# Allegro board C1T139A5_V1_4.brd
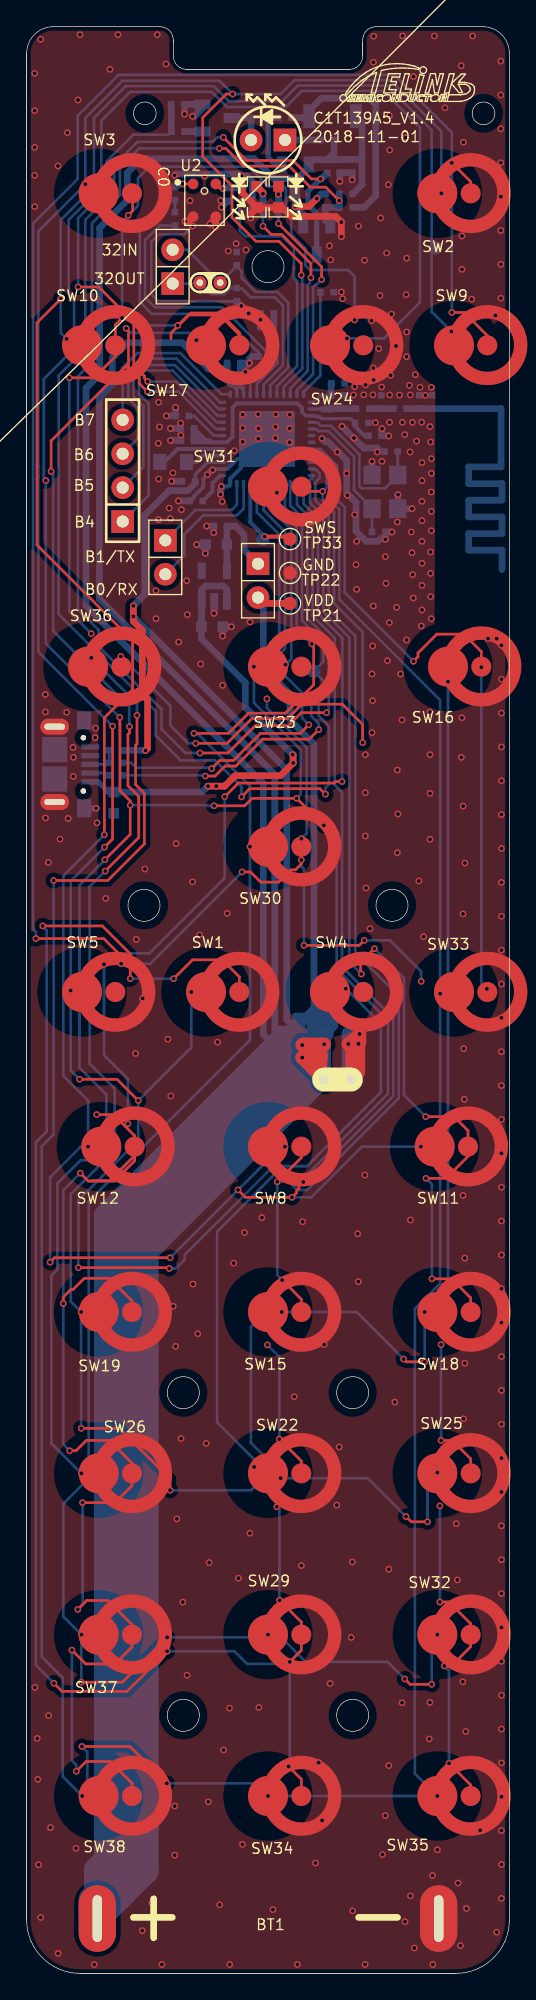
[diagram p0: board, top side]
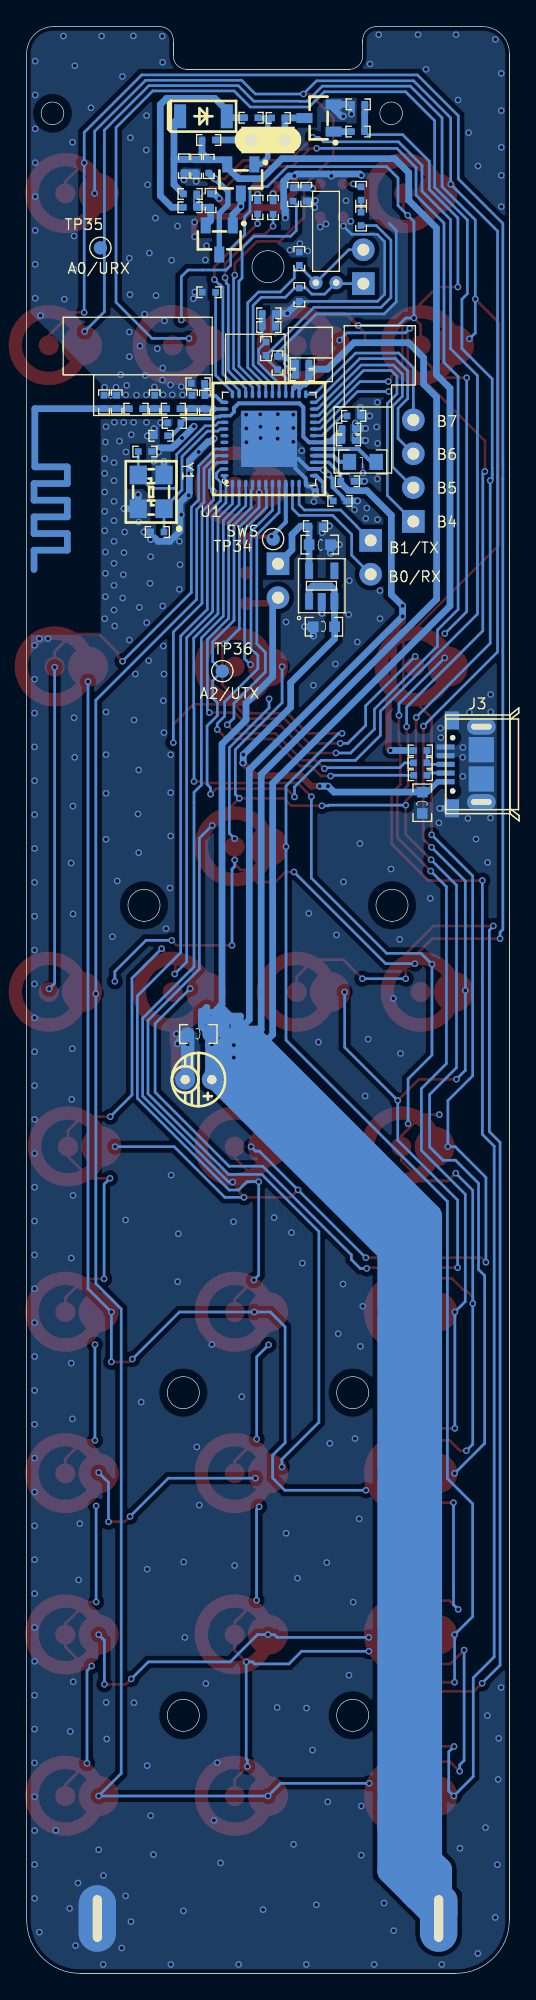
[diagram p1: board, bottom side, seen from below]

Outline 36.2 x 146 mm; copper layers: TOP, BOTTOM. Coordinates in mm from the lower left corner of the outline.
Outline path: circle c8.8,80.1 r1.2 ; circle c8.86,139.5 r0.85 ; circle c11.75,43.55 r1.2 ; circle c11.75,19.35 r1.2 ; circle c18.1,128 r1.2 ; circle c24.45,43.55 r1.2 ; circle c24.45,19.35 r1.2 ; circle c27.4,80.1 r1.2 ; circle c34.26,139.5 r0.85 ; 0,144 0,4 ; 0,144 arc(0.59,145.41) 2,146 10,146 arc(10.71,145.71) 11,145 ; 0,144 0,4 ; 0,4 arc(1.17,1.17) 4,0 ; 4,0 32.2,0 ; 4,0 32.2,0 ; 32.2,0 arc(35.03,1.17) 36.2,4 36.2,144 arc(35.61,145.41) 34.2,146 26.2,146 arc(25.49,145.71) 25.2,145 25.2,144.8 ; 11,145 11,144.8 ; 11,145 11,144.8 ; 11,144.8 11,143.8 arc(11.29,143.09) 12,142.8 ; 12,142.8 24.2,142.8 ; 12,142.8 24.2,142.8 ; 24.2,142.8 arc(24.91,143.09) 25.2,143.8 ; 25.2,144.8 25.2,143.8 ; 25.2,144.8 25.2,143.8

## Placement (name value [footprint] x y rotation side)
BT1  3V_2xAAA  [BAT_2DIP]  18.1 4.11 0 top
C1  0.1uF  [0402]  25.13 116.29 180 bottom
C2  2.2uF  [0402]  26.13 115.32 180 bottom
C4  1uF  [0402]  22.53 126.08 0 bottom
C7  1uF  [0402]  15.53 120.77 180 bottom
C8  1uF  [0402]  12.71 110.43 0 bottom
C10  1uF  [0402]  11.67 116.8 0 bottom
C12  4.7uF  [0402]  24.41 135.55 270 bottom
C13  4.7uF  [0402]  15.23 133.41 270 bottom
C16  10uF  [0603C]  23.33 70.45 0 bottom
C17  10pF  [0402]  17.39 120.78 90 bottom
C18  1uF  [0402]  11.12 133.49 90 bottom
C19  NC  [0402]  27.33 114.13 0 bottom
C20  NC  [0402]  26.4 108.1 180 bottom
C21  NC  [0402]  15.75 128.6 270 bottom
C22  NC  [0402]  15.75 125.9 90 bottom
C23  10pF  [0402]  18.04 123.48 180 bottom
C24  1uF  [0402]  18.04 124.5 180 bottom
C25  1uF  [0402]  12.06 114.96 180 bottom
C26  0.1uF  [0402]  23.49 135.52 270 bottom
C27  1uF  [0402]  12.14 111.91 0 bottom
C28  1uF  [0402]  15.53 119.84 180 bottom
C29  0.1uF  [0402]  12.05 115.86 0 bottom
C30  2.7pF  [0402C]  23.8 117.85 270 bottom
C31  18pF  [0402]  23.35 119.25 0 bottom
C32  2.2pF  [0402C]  26.6 117.85 270 bottom
C33  220pF  [0402C]  25.2 117.35 0 bottom
C34  1.5pF  [0402C]  29.45 117.85 270 bottom
C35  1.2pF  [0402]  30.4 117.85 270 bottom
C39  NC/10uF  [0603C]  13.9 101 0 bottom
C40  NC/10uF  [0603C]  14.22 107.15 180 bottom
C41  NC/0.1uF  [0402]  14.53 108.54 180 bottom
C42  NC/10uF  [0603C]  6.53 87.79 270 bottom
CD1  220uF/10V  [CD2P0_4P0B]  23.31 67.03 0 bottom
D1  Red_LED  [0603-LED]  17.25 133.23 270 top
D2  Red_LED  [0603-LED]  18.89 133.23 270 top
D4  1N4148  [SOD80]  22.94 139.28 180 bottom
D5  LED  [LED_TH_2P54MM_2PIN]  18.1 137.5 0 top
J3  NC/USB_MiniABF  [MICROUSB_DIP]  4.78 89.37 90 bottom
J5  NC/HEADER 4  [HDR254F-1X4X850]  7.2 116.51 270 top
J9  NC/HEADER 2  [HDR254F-1X2X850]  10.4 104.93 90 top
J10  HEADER 2  [HDR254F-1X2X850]  10.95 129.27 270 top
J36  NC/2PIN  [HDR254F-1X2X850]  17.35 103.18 90 top
L3  47UH  [0805L]  10.99 113.36 0 bottom
L4  1.3nH  [0402C]  22.83 117.82 270 bottom
L7  1.5nH  [0402C]  28 117.35 0 bottom
Q2  C1815  [SOT-23]  14.27 139.15 90 bottom
Q3  A1015  [SOT-23]  20.14 134.58 0 bottom
Q4  C1815  [SOT-23]  21.76 130 0 bottom
R1  1K  [0402]  18.88 132.45 90 bottom
R2  1K  [0402]  17.72 132.44 90 bottom
R3  0R  [0402]  16.22 133.41 90 bottom
R4  NC/1.5K  [0402]  6.68 91.71 0 bottom
R7  1  [0402]  22.55 137.5 0 bottom
R8  NC  [0402]  11.34 140.17 180 bottom
R9  100  [0402]  11.35 138.13 0 bottom
R10  10K  [0402]  22.54 135.52 90 bottom
R11  10K  [0402]  22.41 132.96 90 bottom
R12  NC  [0402]  23.94 133.45 180 bottom
R13  47K  [0402]  23.95 132.45 180 bottom
R14  22K  [0402]  19.37 139.17 0 bottom
R15  10K  [0402]  17.33 139.16 0 bottom
R16  NC  [0402]  18.25 121.85 90 bottom
R17  000R  [0402]  11.12 131.59 90 bottom
R69  NC/33  [0402]  6.69 90.79 180 bottom
R70  NC/33  [0402]  6.68 89.86 180 bottom
SW1  SW2PIN  [SW_OUT6_IN3]  13.45 73.6 180 top
SW2  SW2PIN  [SW_OUT6_IN3]  30.8 133.5 180 top
SW3  SW2PIN  [SW_OUT6_IN3]  5.4 133.5 180 top
SW4  SW2PIN  [SW_OUT6_IN3]  22.75 73.6 180 top
SW5  SW2PIN  [SW_OUT6_IN3]  4.15 73.6 180 top
SW8  SW2PIN  [SW_OUT6_IN3]  18.1 62 180 top
SW9  SW2PIN  [SW_OUT6_IN3]  32.05 122.1 180 top
SW10  SW2PIN  [SW_OUT6_IN3]  4.15 122.1 180 top
SW11  SW2PIN  [SW_OUT6_IN3]  30.6 62 180 top
SW12  SW2PIN  [SW_OUT6_IN3]  5.6 62 180 top
SW15  SW2PIN  [SW_OUT6_IN3]  18.1 49.6 180 top
SW16  SW2PIN  [SW_OUT6_IN3]  31.6 98 180 top
SW17  SW2PIN  [SW_OUT6_IN3]  13.45 122.1 180 top
SW18  SW2PIN  [SW_OUT6_IN3]  30.8 49.6 180 top
SW19  SW2PIN  [SW_OUT6_IN3]  5.4 49.6 180 top
SW22  SW2PIN  [SW_OUT6_IN3]  18.1 37.5 180 top
SW23  SW2PIN  [SW_OUT6_IN3]  18.1 98 180 top
SW24  SW2PIN  [SW_OUT6_IN3]  22.75 122.1 180 top
SW25  SW2PIN  [SW_OUT6_IN3]  30.8 37.5 180 top
SW26  SW2PIN  [SW_OUT6_IN3]  5.4 37.5 180 top
SW29  SW2PIN  [SW_OUT6_IN3]  18.1 25.4 180 top
SW30  SW2PIN  [SW_OUT6_IN3]  18.1 84.5 180 top
SW31  SW2PIN  [SW_OUT6_IN3]  18.1 111.5 180 top
SW32  SW2PIN  [SW_OUT6_IN3]  30.8 25.4 180 top
SW33  SW2PIN  [SW_OUT6_IN3]  32.05 73.6 180 top
SW34  SW2PIN  [SW_OUT6_IN3]  18.1 13.3 180 top
SW35  SW2PIN  [SW_OUT6_IN3]  30.8 13.3 180 top
SW36  SW2PIN  [SW_OUT6_IN3]  4.6 98 180 top
SW37  SW2PIN  [SW_OUT6_IN3]  5.4 25.4 180 top
SW38  SW2PIN  [SW_OUT6_IN3]  5.4 13.3 180 top
TP21  VDD  [TP100]  19.75 102.74 0 top
TP22  GND  [TP100]  19.75 105.03 0 top
TP33  SWS  [TP100]  19.75 107.57 0 top
TP34  SWS  [TP100]  17.72 107.57 180 bottom
TP35  URX  [TP100]  30.67 129.41 180 bottom
TP36  UTX  [TP100]  21.53 97.66 180 bottom
U1  TLSR8258F512ET48  [QFN_7X7_48PIN_0P5_4P20X4P20]  18.02 115.08 90 bottom
U2  GA-BFA423-A83-1  [GA_BFA423_A83]  13.33 132.97 0 top
U5  NC/XC6219_3.3V_SOT-23-5  [SOT-23-5]  14.07 104.04 180 bottom
Y1  24MHz-12pF-+/-20ppm  [OSCCC250X320X110]  26.87 111.11 0 bottom
Y2  NC/32.768KHz - 9pf - +/-20ppm  [OSC_2X6]  13.75 130.8 270 bottom

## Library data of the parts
BT1 = BATTERY_2xAAA_3V
C1 C26 C41 = C1005X5R1C104K
C2 = C1005X5R1A225K
C4 C8 = C1005X5R1C105K
C7 = C1608X5R1C105M_0
C10 = C1005X5R1C105K_0
C12 = C1608X5R1A226M
C13 C17 C18 C23-C25 = C1608X5R0J475M
C16 = C1608X5R0J106M
C19-C22 C30 C32-C34 = C1608_NC
C27 C29 = C1005X5R1C105K_1
C28 = C1005X5R1C105K_2
C31 = C1005C0G1H100D
C35 = C1005_NC
C39 C40 C42 = C1608X5R1A106K
CD1 = CD_220uF_16V
D1 D2 = 0603D_Red
D4 = Diode_1N4148
D5 = Led_Th_3mm_1: User Part Number: partnum; Tolerance: RichardLC
J3 = USB_MiniABF_2
J5 = HEADER 4: User Part Number: pn; Tolerance: RichardLC
J9 J10 = HEADER 2: User Part Number: pn; Tolerance: RichardLC
J36 = B2S_2: User Part Number: pn; Tolerance: RichardLC
L3 = IND_0
L4 L7 = MLK1608_000R
Q2 Q4 = NPN_C1815
Q3 = PNP_A1015
R1-R4 R16 R17 = RS0402K472JT
R7 = RS0805K1R0JT
R8 R12 = RS0402_NC
R9 = RS0402K101JT
R10 R11 R15 = RS0402K103JT
R13 = RS0402K473JT
R14 = RS0402K223JT
R69 R70 = RS0402K330JT
SW1-SW5 SW8-SW12 SW15-SW19 SW22-SW26 SW29-SW38 = SW2PIN_0
TP21 TP22 TP33-TP36 = TestPad100
U1 = TLSR8258F512ET48
U2 = MULPS4CX-RM5_0
U5 = XC6219_1.3V_SOT-23-5
Y1 = CRYSTAL4/SM_0: Tolerance: RichardLC
Y2 = OSC_2x6_2pin_16Mhz

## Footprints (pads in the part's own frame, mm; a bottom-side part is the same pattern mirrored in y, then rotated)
0402
  rect 0.5x0.5 smd: 1(-0.5,0) 2(0.5,0)
0402C
  rect 0.5x0.5 smd: 1(-0.5,0) 2(0.5,0)
0603-LED
  rect 0.8x0.8 smd: A(-0.8,0) C(0.8,0)
0603C
  rect 0.8x0.8 smd: 1(-0.8,0) 2(0.8,0)
0805L
  rect 1x1.2 smd: 1(-1,0) 2(1,0)
BAT_2DIP
  oval 2.8x5 hole 0.7x3.5: 1(-12.8,0) 2(12.8,0)
CD2P0_4P0B
  round 1.5 hole 0.7: 1(-1,0) 2(1,0)
GA_BFA423_A83
  round 0.8 smd: 1(-0.85,1.23) 2(-0.85,-1.23) 3(0.85,-1.23) 4(0.85,1.23)
HDR254F-1X2X850
  rect 1.7x1.7 hole 0.9: 1(2.54,0)
  round 1.7 hole 0.9: 2(0,0)
HDR254F-1X4X850
  rect 1.7x1.7 hole 0.9: 1(7.62,0)
  round 1.7 hole 0.9: 2(5.08,0) 3(2.54,0) 4(0,0)
LED_TH_2P54MM_2PIN
  rect 1.7x1.7 hole 0.9: A(1.27,0)
  round 1.7 hole 0.9: C(-1.27,0)
MICROUSB_DIP
  round 0.4 hole 0.6 unplated: (-0.7,-0.525) (3.3,-0.525)
  rect 0.4x1.35 smd: 1(0,0) 2(0.65,0) 3(1.3,0) 4(1.95,0) 5(2.6,0)
  oval 1.2x2.15 hole 0.45x1.55: 6(-1.525,-2.675) 7(4.125,-2.675)
  rect 1.9x1.9 smd: 8(0.2,-2.675) 9(2.4,-2.675)
  rect 1.35x1.07 smd: 10(-1.996,-0.468) 11(4.596,-0.468)
OSC_2X6
  round 1 hole 0.5: 1(4,0.76) 2(4,-0.76)
OSCCC250X320X110
  rect 1.3x1.4 smd: 1(-0.965,1.265) 2(-0.965,-1.265) 3(0.965,-1.265) 4(0.965,1.265)
QFN_7X7_48PIN_0P5_4P20X4P20
  oval 0.6x0.26 smd: 1(-3.35,2.75) 2(-3.35,2.25) 3(-3.35,1.75) 4(-3.35,1.25) 5(-3.35,0.75) 6(-3.35,0.25) 7(-3.35,-0.25) 8(-3.35,-0.75) 9(-3.35,-1.25) 10(-3.35,-1.75) 11(-3.35,-2.25) 12(-3.35,-2.75) 25(3.35,-2.75) 26(3.35,-2.25) 27(3.35,-1.75) 28(3.35,-1.25) 29(3.35,-0.75) 30(3.35,-0.25) 31(3.35,0.25) 32(3.35,0.75) 33(3.35,1.25) 34(3.35,1.75) 35(3.35,2.25) 36(3.35,2.75)
  oval 0.26x0.6 smd: 13(-2.75,-3.35) 14(-2.25,-3.35) 15(-1.75,-3.35) 16(-1.25,-3.35) 17(-0.75,-3.35) 18(-0.25,-3.35) 19(0.25,-3.35) 20(0.75,-3.35) 21(1.25,-3.35) 22(1.75,-3.35) 23(2.25,-3.35) 24(2.75,-3.35) 37(2.75,3.35) 38(2.25,3.35) 39(1.75,3.35) 40(1.25,3.35) 41(0.75,3.35) 42(0.25,3.35) 43(-0.25,3.35) 44(-0.75,3.35) 45(-1.25,3.35) 46(-1.75,3.35) 47(-2.25,3.35) 48(-2.75,3.35)
  rect 4.2x4.2 smd: 49(0,0)
SOD80
  rect 0.9x1.8 smd: A(-1.75,0) C(1.75,0)
SOT-23
  rect 0.75x1.2 smd: 1(-1.016,-1.092) 2(1.016,-1.092) 3(0,1.092)
SOT-23-5
  rect 0.6x1.25 smd: 1(-0.95,-1.145) 2(0,-1.145) 3(0.95,-1.145) 4(0.95,1.145) 5(-0.95,1.145)
SW_OUT6_IN3
  round 3 smd: 1(0,0)
  custom 1.5x1.5 smd: 2(-2.5,0)
TP100
  round 1 smd: 1(0,0)

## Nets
GND: BT1.2(-) C1.1 C2.1 C4.2 C7.1 C8.1 C10.1 C12.2 C13.2 C16.2 C17.2 C19.1 C20.1 C21.1 C22.1 C23.2 C24.2 C25.2 C26.2 C27.1 C28.1 C29.1 C30.1 C31.2 C32.1 C34.1 C35.1 C39.2 C40.2 C41.2 C42.2 CD1.2 D1.C(CATHODE) D2.C(CATHODE) J3.4(ID) J3.5(GND) J3.6(S1) J3.7(S2) J3.8(S3) J3.9(S4) J3.10(S5) J3.11(S6) Q2.2(E) R8.1 TP22.1(TP) U1.12(DVSS#12) U1.14(DVSS#14) U1.49(GND) U2.2(GND#2) U2.3(GND#3) U5.2(VSS) Y1.2 Y1.4
VDD1V2: C1.2 C2.2 C25.1 C29.2 U1.18(VDD1V2) U1.39(AVDD1V2)
TL_32INPUT: C21.2 J10.2 U1.31(P1/URX/I2CCK/32KI/PGAN1/C[3]) Y2.2
TL_32OUTPUT: C22.2 J10.1 U1.30(P0/7816TRX/I2CSDA/32KO/PGAP1/C[) Y2.1
TL_AMICBIAS: R3.1 U1.32(P2/UCTS/P0N/BIAS/C[4])
TL_AMICSN: C23.1 C24.1 R16.2 U1.29(I2CCK/P1N/P0/PGAN0/C[1])
TL_AMICSP: C17.1 R16.1 R17.1 U1.28(I2CSDA/P4N/URTS/PGAP0/C[0])
TL_B0: J9.2 U1.10(P3/URX/ATSEL1/B[0])
TL_B1: J9.1 U1.11(P4/UTX/ATSEL2/B[1])
TL_B4: J5.1 U1.22(SDMP0/P4/B[4])
TL_B5: J5.2 U1.23(SDMN0/P5/B[5])
TL_B6: J5.3 U1.24(SDMP1/DI/URTS/B[6])
TL_B7: J5.4 U1.25(SDMN1/DO/URX/B[7])
TL_COL0: SW1.1 SW2.1 SW3.1 SW4.1 SW5.1 U1.33(P3N/URX/ATSEL0/C[5])
TL_COL1: SW8.1 SW9.1 SW10.1 SW11.1 SW12.1 TP35.1(TP) U1.2(DMIC_DI/P0N/URX/A[0])
TL_COL2: SW15.1 SW16.1 SW17.1 SW18.1 SW19.1 U1.20(P5/UCTS/CYC2LNA/B[2])
TL_COL3: SW22.1 SW23.1 SW24.1 SW25.1 SW26.1 U1.6(CK/URTS/P2/A[4])
TL_COL4: SW29.1 SW30.1 SW31.1 SW32.1 SW37.1 U1.5(DI/UCTS/P1/A[3])
TL_COL5: SW33.1 SW34.1 SW35.1 SW36.1 SW38.1 U1.45(P1N/I2SSDI/7816TRX/D[3])
TL_DM: R70.1 U1.7(DM/A[5])
TL_DP: R69.1 U1.8(DP/A[6])
TL_IRCONTROL: Q4.2(E) R11.1 R12.2 R13.2 U1.3(DMIC_CK/7816CLK/I2SCK/A[1])
TL_IRIN: Q4.3(C) R10.1 TP36.1(TP) U1.4(DO/UTX/P0/A[2])
TL_IROUT: R8.2 R9.1 U1.21(P0N/URTS/CYC2PA/B[3])
TL_LED1: R2.1 U1.34(CYC2LNA/ATSEL1/P4N/C[6])
TL_LED2: R1.1 U1.35(CYC2PA/ATSEL2/P5N/C[7])
TL_ROW0: SW1.2 SW8.2 SW15.2 SW22.2 SW29.2 SW34.2 U1.47(P0/P0N/D[5])
TL_ROW1: SW2.2 SW9.2 SW16.2 SW23.2 SW30.2 SW33.2 U1.44(CN/I2SLR/P3/D[2])
TL_ROW2: SW3.2 SW10.2 SW17.2 SW24.2 SW31.2 SW36.2 U1.46(SWM/I2SSDO/P2N/D[4])
TL_ROW3: SW4.2 SW11.2 SW18.2 SW25.2 SW32.2 SW35.2 U1.48(CN/URX/ATSEL0/D[6])
TL_ROW4: SW5.2 SW12.2 SW19.2 SW26.2 SW37.2 SW38.2 U1.1(CK/I2SBCK/7816TRX/D[7])
TL_RST: C4.1 U1.36(RESETB)
TL_SWS: TP33.1(TP) TP34.1(TP) U1.9(SWS/URTS/A[7])
TL_VBUS: C39.1 C42.1 J3.1(V_BUS) U5.1(VIN) U5.3(CE)
TL_VDD: BT1.1(+) C7.2 C12.1 C16.1 C26.1 C27.2 C28.2 CD1.1 D4.A J36.2 Q3.2(E) R4.2 R7.2 R10.2 R12.1 TP21.1(TP) U1.15(VDD_IO) U1.26(VDD3) U1.27(VDDIO_AMS)
TL_XC1: C19.2 U1.40(XC1) Y1.3
TL_XC2: C20.2 U1.41(XC2) Y1.1
N21000893: D2.A(ANODE) R1.2
N21007782: D1.A(ANODE) R2.2
N21036936: C13.1 R3.2 U2.4(VDD)
N21036981: C18.1 R17.2
N21036983: C18.2 U2.1(OUTPUT)
N21081547: C40.1 C41.1 J36.1 U5.5(VOUT)
N21081898: J3.3(D+) R4.1 R69.2
N21081900: J3.2(D-) R70.2
N21088560: C10.2 U1.19(VDD_F)
N21088582: L3.1 U1.17(VDCDC)
N21088586: L3.2 U1.16(VDCDC_SW)
N21088616: C8.2 U1.13(VDD1V)
N21092386: C30.2 C33.1 L4.2 U1.38(ANT)
N21092388: C31.1 L4.1 U1.37(VANT)
N21092398: C32.2 C33.2 L7.1
N21092424: C34.2 C35.2 L7.2
N21108187: D5.A(ANODE) R7.1
N21108227: D4.C R13.1 R14.2
N21108333: Q2.1(B) R9.2
N21108349: D5.C(CATHODE) Q2.3(C) R15.1
N21108369: Q3.3(C) Q4.1(B) R11.2
N21108379: Q3.1(B) R14.1 R15.2

Pads without a net: U1 42 43; U5 4

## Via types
v1: diameter 0.5, hole 0.3, TOP to BOTTOM, 557 vias

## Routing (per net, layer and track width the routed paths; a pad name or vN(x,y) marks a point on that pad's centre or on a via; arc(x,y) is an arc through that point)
GND: length 140.9
  TOP w0.5: v1(23.61,130.24) v1(23.61,131.34) 23.18,131.77 19.84,131.77 19.17,132.43 D2.C D1.C ; U2.2 12.14,131.4 v1(11.88,131.4) ; 14.18,131.63 U2.3 ; 14.18,131.63 v1(13.75,131.2) ; 14.18,131.63 v1(14.18,130.98) ; v1(16.12,134.8) 16.12,133.58 17.25,132.45 D1.C ; v1(16.8,131.66) 16.8,131.93 17.25,132.39 D1.C
  TOP w1: 24.41,67.13 24.41,69.41 v1(24.13,69.7) 24.21,69.7 v1(24.97,70.45) 24.97,69.79 v1(24.89,69.71) 24.89,67.61 24.41,67.13 ; 24.41,67.13 CD1.2
  BOTTOM w0.2: U1.49 17.2,114.86 v1(16.2,114.86) ; U1.49 18.67,115.85 v1(18.67,115.99) ; U1.49 18.02,116.28 v1(17.36,116.94) ; U1.49 19.21,114.83 v1(19.72,114.83) ; U1.49 18.1,115.15 v1(18.66,115.15) ; U1.49 19.57,115.7 v1(19.73,115.87) ; U1.49 17.45,115.87 v1(17.39,115.87) ; U1.49 19.6,116.9 v1(19.74,116.9) ; U1.49 16.85,116.9 v1(16.2,116.9) ; U1.49 18.64,116.88 v1(18.68,116.92) ; v1(12.45,131.05) 11.83,130.43 9.91,130.43 9.35,129.87 9.35,125.93 9.89,125.4 15.27,125.4 15.27,125.4 C22.1 ; C17.2 17.39,121.59 17.25,121.73 17.21,121.73 14.49,124.45 9.39,124.45 8.48,125.36 8.48,130.71 9.01,131.24
  BOTTOM w0.25: 14.08,112.83 13.95,112.7
  BOTTOM w0.3: 16.52,113.58 U1.49 ; 16.52,113.58 15.81,113.58 15.05,112.83 U1.14 14.03,112.83 v1(13.95,112.75) ; 16.52,113.58 16.05,113.11 16.05,112.89 15.27,112.1 U1.12 15.05,111.51 v1(14.6,111.51) ; v1(13.55,112.4) 13.24,112.09 13.24,111.46 12.49,110.72 12.49,110.59
  BOTTOM w0.5: v1(14.55,132.95) 14.59,132.91 15.06,132.91 ; v1(11.1,134.85) 11.2,134.95 13.2,134.95 v1(13.35,134.8) 13.5,134.95 15.97,134.95 v1(16.12,134.8) 16.53,134.8 16.92,134.41 16.92,132.41 16.8,132.29 v1(16.8,131.66) ; v1(26.9,107.55) 26.9,107.55 C20.1 v1(27.4,108.1) ; v1(24.41,134.51) C12.2 23.52,135.05 C26.2 v1(23.49,134.4) ; C23.2 v1(17.54,124.02) C24.2 v1(16.65,124.5) v1(16.1,125.05) C22.1 ; v1(11.56,115.36) C25.2 v1(10.78,114.96) ; v1(5.22,87.38) J3.10 ; v1(10.47,116.8) C10.1 v1(11.17,117.44) ; v1(16.41,120.11) 16.14,119.84 C28.1 16.03,120.48 ; v1(16.41,120.11) 16.03,120.48 ; v1(16.41,120.11) 16.41,120.47 v1(16.7,120.76) ; v1(26.65,115.85) 26.63,115.83 C2.1 27.13,115.32 v1(27.15,115.3) ; v1(14.6,111.51) 14.6,111.3 14.53,111.23 v1(14.53,110.92) ; 24.19,70.45 24.89,69.75 v1(24.89,69.71) ; 24.19,70.45 v1(24.97,70.45) ; 24.19,70.45 C16.2 ; v1(13.4,106.5) 13.42,106.52 C40.2 12.75,107.15 v1(12.75,107.15) ; v1(15.35,101) 15.35,101 C39.2 14.7,100.3 v1(14.7,100.3) ; 26.6,107.66 26.34,107.4 25.46,107.4 24.7,108.17 24.7,110.32 24.4,110.62 24.4,110.62 24,111.02 24,113.47 22.59,114.88 22.39,114.88 v1(22.15,115.11) ; v1(27.85,110.9) 27.83,110.88 Y1.4 28.89,109.84 v1(28.9,109.85) ; C8.1 v1(11.38,110.43) ; v1(23.65,116.03) 23.65,116.03 23.94,115.73 23.94,115.72 25.04,114.62 25.08,114.62 25.3,114.4 26.3,114.4 v1(26.3,114.1) ; C17.2 16.89,121.28 16.7,121.08 v1(16.7,120.76) ; C27.1 v1(10.86,111.91) ; v1(14.03,108.05) C41.2 13.51,108.54 v1(13.5,108.55) ; v1(25.9,113.4) 25.9,113.4 Y1.2 ; U5.2 14.07,102.02 v1(14.05,102) ; 15.06,132.91 C13.2 ; 15.06,132.91 v1(14.6,132.45) ; v1(10.78,115.86) C29.1 v1(11.55,116.27) ; v1(16.7,120.76) 16.69,120.77 C7.1 16.03,120.48 ; v1(13.55,112.4) 13.9,112.75 v1(13.95,112.75) ; v1(12.44,139.27) 12.46,139.29 12.6,139.29 13.18,139.87 Q2.2 13.17,140.17 R8.1 v1(11.84,139.45)
  BOTTOM w1: C16.2 v1(24.13,69.7) 24.13,67.22 CD1.2
  vias: v1(0.6,142.5) v1(0.6,139.7) v1(0.6,136.95) v1(0.6,134.85) v1(0.6,132.5) v1(0.62,21.44) v1(0.8,17.62) v1(0.84,14.55) v1(0.9,8.14) v1(1.05,145.05) v1(1.06,4.19) v1(1.4,95.92) v1(1.4,94.6) v1(1.41,86.65) v1(1.63,83.32) v1(1.65,19.33) v1(1.78,10.93) v1(2.35,135.55) v1(2.36,1.5) v1(2.5,85.07) v1(3,94.58) v1(3.05,138.05) v1(3.11,86.62) v1(3.48,91.94) v1(3.5,91.2) v1(3.49,89.77) v1(3.71,9.38) v1(3.85,140.5) v1(4,145.4) v1(5.13,92.68) v1(5.07,0.67) v1(5.16,93.39) v1(5.28,86.28) v1(5.93,80.62) v1(6.25,142.8) v1(6.85,145.4) v1(8.22,77.54) v1(8.16,68.99) v1(8.7,73.12) v1(8.67,3.2) v1(8.87,82.82) v1(9.4,5.27) v1(9.7,103.7) v1(9.7,101.6) v1(9.8,145.4) v1(9.9,117.83) v1(9.88,114.75) v1(9.9,112.08) v1(9.89,109.03) v1(9.96,115.98) v1(10.15,0.67) v1(10.45,143.2) v1(10.59,70.07) v1(10.68,109.89) v1(10.77,109.11) v1(10.81,65.8) v1(10.97,112.53) v1(10.99,50.03) v1(11.1,12.55) v1(11.1,8.86) v1(11.21,84.73) v1(11.17,47.02) v1(11.26,34.09) v1(11.4,99.85) v1(11.61,109.77) v1(11.58,40.11) v1(11.71,27.84) v1(12,104.45) v1(12.03,22.36) v1(12.05,101.9) v1(12.25,132.95) v1(12.44,81.86) v1(12.48,51.69) v1(12.83,47.97) v1(12.97,77.88) v1(13.05,98.2) v1(13.46,39.75) v1(13.62,12.86) v1(13.69,30.81) v1(14.32,69.84) v1(14.47,5.14) v1(14.66,110.38) v1(14.7,96.6) v1(14.77,16.75) v1(15.04,79.5) v1(15.12,129.18) v1(15.22,19.89) v1(15.23,0.67) v1(15.53,53.27) v1(15.57,114.2) v1(15.71,129.73) v1(15.89,29.64) v1(16.2,115.9) v1(16.18,9.67) v1(16.34,55.56) v1(16.45,129.25) v1(16.74,33.01) v1(16.75,101.35) v1(17.38,115.09) v1(17.42,19.94) v1(17.64,56.68) v1(18.47,4.78) v1(20.07,43.25) v1(20.31,0.67) v1(20.61,30.58) v1(20.7,56.37) v1(21.66,8.28) v1(21.91,15.8) v1(22.16,11.47) v1(22.31,47.16) v1(22.71,129.56) v1(22.8,128.51) v1(22.76,21.73) v1(23.3,114.1) v1(23.26,35.12) v1(23.44,39.48) v1(23.6,126.1) v1(23.7,125.6) v1(24,112.5) v1(24.05,110.85) v1(24.33,25.19) v1(24.42,30.85) v1(24.45,4.69) v1(24.51,118.38) v1(24.6,119) v1(24.55,115.15) v1(24.6,109.4) v1(24.7,105.65) v1(24.75,107.4) v1(24.75,103.8) v1(24.83,55.47) v1(24.89,131.04) v1(24.87,51.87) v1(25.33,128.48) v1(25.28,118.39) v1(25.41,119.13) v1(25.4,91.4) v1(25.4,88.55) v1(25.4,85.3) v1(25.45,81.4) v1(25.37,59.87) v1(25.39,0.67) v1(25.75,78.35) v1(25.87,123.94) v1(25.95,99.55) v1(25.9,97.45) v1(25.95,95.45) v1(25.9,93.05) v1(26.03,145.28) v1(26.01,143.33) v1(26,120.4) v1(26.02,119.5) v1(25.97,118.39) v1(26,102.55) v1(26.15,116.3) v1(26.4,121.85) v1(26.55,131.65) v1(26.5,125.83) v1(26.62,118.98) v1(26.65,113.4) v1(26.69,8.91) v1(26.9,106.25) v1(26.95,104.25) v1(26.89,11.83) v1(27,129.02) v1(27.13,134.14) v1(27.05,98.45) v1(27.21,139.33) v1(27.23,136.75) v1(27.23,118.38) v1(27.22,116.33) v1(27.2,101.3) v1(27.16,30.31) v1(27.16,15.58) v1(27.3,119.85) v1(27.36,124.44) v1(27.61,42.85) v1(27.7,122.05) v1(27.8,108.85) v1(27.75,102.45) v1(27.8,90.25) v1(27.8,84.05) v1(27.85,86.95) v1(27.96,118.37) v1(28.05,97.45) v1(28.15,94) v1(28.2,145.31) v1(28.18,116.33) v1(28.15,20.3) v1(28.42,137.67) v1(28.36,115.4) v1(28.38,3.88) v1(28.5,128.64) v1(28.46,125.9) v1(28.5,123.1) v1(28.5,121.25) v1(28.5,100) v1(28.7,119.1) v1(28.77,118.38) v1(28.75,114.1) v1(28.78,56.5) v1(28.78,5.81) v1(28.92,116.33) v1(28.85,108.1) v1(28.9,106.55) v1(28.95,104.9) v1(29.02,142.26) v1(29,103.15) v1(29.15,119.9) v1(29.07,1.9) v1(29.24,114.91) v1(29.41,81.93) v1(29.5,118.95) v1(29.62,116.34) v1(29.65,113.3) v1(29.65,111.95) v1(29.65,110.4) v1(29.65,108.95) v1(29.65,107.4) v1(29.65,105.75) v1(29.65,104.1) v1(29.65,102.25) v1(29.6,101.05) v1(29.77,77.75) v1(29.9,118.35) v1(30.25,116) v1(30.25,94.6) v1(30.25,91.4) v1(30.25,88.5) v1(30.25,85.05) v1(30.24,20.32) v1(30.2,17.58) v1(30.3,114.85) v1(30.3,106.6) v1(30.3,105) v1(30.3,103.25) v1(30.35,118.95) v1(30.35,113.6) v1(30.35,112.5) v1(30.35,111.1) v1(30.35,109.65) v1(30.35,108.2) v1(30.35,101.6) v1(30.44,7.34) v1(30.47,0.67) v1(30.58,145.3) v1(30.8,9.27) v1(31.38,139.92) v1(32.22,33.73) v1(32.31,29.5) v1(32.35,6.77) v1(32.53,2.08) v1(32.59,143.07) v1(32.65,130.3) v1(32.65,127.8) v1(32.64,94.17) v1(32.6,91.2) v1(32.73,87.54) v1(32.72,79.45) v1(32.72,58.34) v1(32.71,21.87) v1(32.76,137.33) v1(32.78,69.35) v1(32.82,65.55) v1(32.77,41.59) v1(32.87,83.27) v1(32.86,53.65) v1(32.86,45.77) v1(32.94,18.14) v1(32.98,4.86) v1(33.44,145.3) v1(33.37,125.56) v1(34.01,10.73) v1(34.6,100.1) v1(35.16,124.34) v1(35.25,100.1) v1(35.25,3.09) v1(35.56,143.42) v1(35.56,140.88) v1(35.56,138.34) v1(35.56,135.8) v1(35.56,133.26) v1(35.56,130.72) v1(35.56,128.18) v1(35.56,125.64) v1(35.61,99.6) v1(35.61,97.06) v1(35.61,94.52) v1(35.61,91.98) v1(35.61,89.44) v1(35.61,86.9) v1(35.61,84.36) v1(35.61,81.82) v1(35.61,79.28) v1(35.61,76.74) v1(35.61,74.2) v1(35.61,71.66) v1(35.61,69.12) v1(35.61,66.58) v1(35.61,64.04) v1(35.61,61.5) v1(35.61,58.96) v1(35.61,56.42) v1(35.61,53.88) v1(35.61,51.34) v1(35.61,48.8) v1(35.61,46.26) v1(35.61,43.72) v1(35.61,41.18) v1(35.61,38.64) v1(35.61,36.1) v1(35.61,33.56) v1(35.61,31.02) v1(35.61,28.48) v1(35.61,25.94) v1(35.61,23.4) v1(35.61,20.86) v1(35.61,18.32) v1(35.61,15.78) v1(35.61,13.24) v1(35.61,10.7) v1(35.61,8.16) v1(35.61,5.62)
VDD1V2: length 21.2
  BOTTOM w0.25: 20.65,117.1 20.92,116.83 U1.39 21.64,116.83 21.71,116.75 21.98,116.75 22.13,116.6 24.32,116.6 C1.2
  BOTTOM w0.3: C1.2 24.63,116.02 25.33,115.32 C2.2 ; 13.45,114.96 13.13,115.28 ; 13.45,114.96 C25.1 12.7,114.83 13.88,114.83 ; 13.45,114.96 13.75,114.96 13.88,114.83 ; 13.13,115.28 12.85,115.28 12.55,114.98 ; 13.13,115.28 C29.2 ; 20.65,117.1 20.65,117.4 20.3,117.75 15.75,117.75 15.45,117.45 15.45,115.25 15.02,114.83 U1.18 13.88,114.83
  BOTTOM w0.5: C29.2 12.55,114.98 C25.1
TL_32INPUT: length 19.1
  BOTTOM w0.2: J10.2 12.04,129.27 Y2.2 15.75,128.04 ; C21.2 15.75,128.04 ; 15.75,128.04 16.13,127.66 16.13,127.15 17.18,126.1 18.81,126.1 19.62,125.3 19.62,120.44 18.27,119.09 U1.31
TL_32OUTPUT: length 16.7
  BOTTOM w0.2: J10.1 12.92,126.73 Y2.1 13.85,125.94 14.81,125.94 15.27,126.4 C22.2 15.8,126.35 16.15,126.35 16.8,125.7 18.61,125.7 19.22,125.09 19.22,120.61 17.77,119.16 U1.30
TL_AMICBIAS: length 18.6
  BOTTOM w0.2: U1.32 18.77,119.02 20.28,120.54 20.28,126.9 20.04,127.14 20.04,129.39 19.15,130.28 16.41,130.28 15.98,130.71 15.98,132.67 R3.1
TL_AMICSN: length 7.1
  BOTTOM w0.2: C23.1 18.54,122.64 R16.2 18.81,121.79 18.81,120.76 17.27,119.22 U1.29
  BOTTOM w0.5: C24.1 C23.1
TL_AMICSP: length 21.7
  BOTTOM w0.2: U1.28 16.77,119.66 C17.1 18.25,121.14 R16.1 14.66,124.94 9.63,124.94 8.88,125.69 8.88,129.99 9.98,131.09 R17.1
TL_B0: length 10.7
  BOTTOM w0.2: J9.2 11.82,106.35 11.82,107.92 13.25,109.35 15.77,109.35 16.27,109.85 U1.10
TL_B1: length 8.1
  BOTTOM w0.2: J9.1 11.45,108.52 11.45,108.54 12.66,109.75 15.37,109.75 15.77,110.15 U1.11
TL_B4: length 19.8
  BOTTOM w0.2: U1.22 14.32,116.83 14.22,116.93 14.22,116.93 10.94,120.21 8.86,120.21 8.43,119.78 8.43,118.46 9.15,117.73 9.15,110.84 J5.1
TL_B5: length 17.8
  BOTTOM w0.2: J5.2 8.75,112.98 8.75,117.54 8.02,118.27 8.02,119.94 8.7,120.62 11.11,120.62 14.07,117.66 14.07,117.65 14.32,117.4 14.33,117.4 14.4,117.33 U1.23
TL_B6: length 15.8
  BOTTOM w0.2: J5.3 8.35,115.12 8.35,117.38 7.62,118.11 7.62,120.18 8.55,121.11 11.22,121.11 14.24,118.08 14.24,118.08 14.5,117.83 U1.24
TL_B7: length 13.7
  BOTTOM w0.2: J5.4 7.2,117.59 7.2,117.59 7.2,120.42 8.29,121.52 11.53,121.52 14.62,118.43 U1.25
TL_COL0: length 212.2
  TOP w0.2: v1(23.94,73.85) 23.68,73.6 SW4.1 ; v1(3.3,73.71) 3.42,73.6 SW5.1 ; v1(3.88,52.93) 10.63,52.93 v1(10.7,52.87) ; v1(5.84,84.46) 6.44,85.07 v1(6.44,93.54) ; SW3.1 4.72,134.18 v1(4.4,134.18) ; SW1.1 v1(12.35,73.6) ; v1(15.44,140.95) 14.97,140.95 13.2,139.19 13.2,136.26 15.4,134.06 15.4,131.7 17.2,129.9 18.93,129.9 20.59,128.23 v1(20.59,127.37) ; SW2.1 v1(31.1,133.5) ; v1(8.37,65.46) 6.78,67.06 v1(3.97,67.06)
  BOTTOM w0.2: v1(6.44,93.54) 0.89,99.1 0.89,112.25 0.88,112.25 0.88,113.04 0.89,113.04 0.89,130.67 v1(4.4,134.18) 4.4,139.16 7.18,141.94 14.46,141.94 v1(15.44,140.95) 19.05,140.95 20.08,141.98 27.27,141.98 31.1,138.15 v1(31.1,133.5) ; v1(3.88,52.93) 3.88,57.99 8.37,62.48 v1(8.37,65.46) 12.35,69.45 v1(12.35,73.6) ; v1(23.94,73.85) 26.57,71.22 26.57,66.08 21.02,60.53 18.5,60.53 11.85,53.89 11.85,53.53 11.18,52.87 v1(10.7,52.87) ; U1.33 19.27,118.96 20.68,120.37 20.68,127.07 20.59,127.16 v1(20.59,127.37) ; v1(5.84,84.46) 3.3,81.93 v1(3.3,73.71) 3.3,67.72 v1(3.97,67.06)
TL_COL1: length 245.1
  TOP w0.2: v1(2.99,122.58) 3.48,122.1 SW10.1 ; v1(31.85,123.14) 32.05,122.94 SW9.1 ; v1(20.75,59.35) 20.41,59.01 20.41,58.85 20.24,58.67 20.24,58.54 v1(19.9,58.2) 16.41,58.2 v1(15.85,58.76) ; v1(5.83,85.39) 5.83,86.05 5.83,86.06 5.83,86.51 5.83,86.52 5.83,94.17 7.95,96.29 7.95,99.95 0.77,107.12 0.77,123.79 v1(2.55,125.57) ; v1(10.76,53.67) 2.09,53.67 v1(1.76,53.33) ; SW8.1 v1(19.37,62) ; SW11.1 v1(29.57,62) ; SW12.1 v1(4.61,62)
  BOTTOM w0.2: v1(29.57,62) 25.14,62 21.34,58.2 v1(19.9,58.2) ; v1(10.76,53.67) v1(15.85,58.76) 18.76,61.66 19.04,61.66 v1(19.37,62) ; U1.2 20.27,110.15 21.45,108.97 21.45,101.8 23.1,100.15 23.1,89.12 23.65,88.57 23.65,87.8 23.65,75.49 27.5,71.64 27.5,65.8 21.05,59.35 v1(20.75,59.35) ; v1(2.99,122.58) 2.55,123.03 v1(2.55,125.57) 2.55,131.51 5.05,134 5.05,139.16 7.42,141.54 14.03,141.54 15.16,140.41 15.21,140.41 15.22,140.4 15.67,140.4 15.68,140.41 19.16,140.41 20.33,141.58 27.03,141.58 30.37,138.24 30.37,129.71 TP35.1 30.37,129.11 30.37,124.62 v1(31.85,123.14) ; v1(5.83,85.39) 2.75,82.32 2.75,67.31 4.61,65.45 v1(4.61,62) 4.06,62 1.76,59.69 v1(1.76,53.33)
TL_COL2: length 207.5
  TOP w0.2: v1(9.05,118.63) 8.44,119.24 8.44,119.62 8.13,119.93 7.64,120.43 7.64,120.45 ; 7.64,120.45 7.64,120.74 ; 7.64,120.45 7.34,120.45 ; SW16.1 v1(31.6,96.88) ; v1(7.46,123.37) 7.64,123.2 7.64,120.74 ; SW18.1 v1(29.85,49.6) ; v1(29.85,45.86) 28.48,45.86 v1(28.27,46.07) ; SW17.1 13.06,122.49 v1(12.73,122.49) ; v1(4.09,40.87) 6.96,40.87 10.76,37.08 v1(10.76,36.23) ; 7.64,120.74 7.34,120.45 ; 7.34,120.45 1.83,114.94 v1(1.83,112.64) ; v1(7.7,93.5) 7.7,93.02 7.59,92.91 7.59,89.08 8.41,88.27 8.41,85.18 v1(5.89,82.67) ; SW19.1 v1(4.09,49.6) ; SW15.1 v1(19.13,49.6)
  BOTTOM w0.2: v1(1.83,112.64) 1.83,112.63 1.99,112.48 1.99,100.68 7.7,94.97 v1(7.7,93.5) ; v1(5.89,82.67) 4.72,81.5 4.72,68.23 6.6,66.35 6.6,61.73 3.3,58.43 3.3,50.38 v1(4.09,49.6) v1(4.09,40.87) ; v1(29.85,45.86) v1(29.85,49.6) 31.6,51.35 v1(31.6,96.88) ; v1(12.73,122.49) 12.18,123.04 7.8,123.04 v1(7.46,123.37) ; v1(10.76,36.23) 16.84,36.23 17.74,37.14 17.74,38.86 16.82,39.79 16.82,48.48 17.93,49.6 v1(19.13,49.6) 24.74,49.6 v1(28.27,46.07) ; v1(9.05,118.63) 11.38,118.63 13.89,116.13 13.89,116.12 14.19,115.83 U1.20
TL_COL3: length 280.9
  TOP w0.2: v1(14.05,87.57) 16.35,87.57 16.91,88.13 v1(20.25,88.13) 21.95,86.43 v1(22.29,86.09) ; v1(6.99,94.2) 6.99,93.72 6.99,93.71 6.99,93.22 7,93.22 7,88.7 7.77,87.93 v1(7.77,87.61) 7.77,85.42 v1(5.87,83.52) ; v1(24.03,122.62) 23.51,122.1 SW24.1 ; v1(19.05,37.14) 18.69,37.5 SW22.1 17.62,37.98 v1(17.06,37.98) ; SW26.1 v1(4.1,37.5) ; SW23.1 19.25,98.15 v1(19.41,98.15) ; SW25.1 v1(30.8,37.55) ; v1(28.45,34.26) 28.85,33.86 v1(30.06,33.86)
  BOTTOM w0.2: v1(7.77,87.61) 13.53,87.61 13.58,87.57 v1(14.05,87.57) ; v1(22.29,86.09) 23.25,85.13 23.25,75.32 27.1,71.47 27.1,65.97 21.06,59.92 18.57,59.92 14.28,55.64 14.28,41.33 17.06,38.55 v1(17.06,37.98) ; v1(19.41,98.15) 19.85,98.59 19.85,101.13 19.85,101.19 19.85,108.3 18.22,109.94 18.22,111.28 18.27,111.33 U1.6 ; v1(30.8,37.55) 30.06,36.82 v1(30.06,33.86) ; v1(6.99,94.2) 1.44,99.75 v1(1.44,111.96) 1.29,112.11 1.29,112.41 1.28,112.42 1.28,112.87 1.29,112.87 1.29,119.58 3.56,121.85 3.56,125.56 3.15,125.97 3.15,131.51 5.6,133.96 5.6,138.95 7.77,141.12 13.87,141.12 15.01,139.98 19.44,139.98 20.64,141.18 26.75,141.18 29.5,138.43 29.5,125.33 26.79,122.62 v1(24.03,122.62) ; v1(5.87,83.52) 3.96,81.61 3.96,67.92 5.98,65.91 5.98,61.99 4.97,60.99 4.04,60.99 2.31,59.25 2.31,52.79 1.85,52.33 1.85,39.75 v1(4.1,37.5) ; v1(19.05,37.14) 25.57,37.14 v1(28.45,34.26) ; v1(17.04,98) 17.04,95.29 20.55,91.78 20.55,88.43 v1(20.25,88.13)
TL_COL4: length 142.8
  TOP w0.2: SW37.1 v1(4.11,25.4) ; SW30.1 v1(16.75,84.5) ; v1(28.36,22.08) 28.76,21.68 v1(30.37,21.68) ; v1(21.38,99.71) 21.53,99.56 21.53,96.64 19.39,94.51 16.64,94.51 15.13,93 v1(12.55,93) ; v1(18.77,111.05) 18.32,111.5 SW31.1 ; v1(4.11,21.83) 7.17,21.83 v1(10.54,25.2)
  BOTTOM w0.2: U1.5 v1(18.77,111.05) 18.77,109.95 20.25,108.47 20.25,101.69 20.25,101.6 20.25,100.84 v1(21.38,99.71) ; v1(12.55,93) 12.8,93 16.75,89.05 v1(16.75,84.5) 16.75,70 4.65,57.9 4.65,37.11 2.75,35.22 2.75,26.75 v1(4.11,25.4) v1(4.11,21.83) ; v1(30.37,21.68) 30.37,24.97 v1(30.8,25.4) ; v1(10.54,25.2) 17.42,25.2 17.62,25.4 v1(18.1,25.4) 18.89,25.4 20.93,23.36 27.08,23.36 v1(28.36,22.08)
TL_COL5: length 234.5
  TOP w0.2: SW36.1 4.6,98.42 v1(4.85,98.66) ; SW38.1 v1(4.17,13.3) ; v1(4.14,17.01) 7.75,17.01 v1(10.51,14.25) ; v1(2.02,81.96) 6.08,81.96 8.83,84.71 8.83,88.5 8.17,89.16 8.17,92.1 8.28,92.21 v1(8.28,94.35)
  BOTTOM w0.2: v1(2.02,81.96) 2.02,62.92 1.14,62.04 1.14,23.74 2.71,22.17 2.71,14.76 v1(4.17,13.3) 4.54,13.68 4.54,16.62 v1(4.14,17.01) ; v1(8.28,94.35) 8.28,95.23 v1(4.85,98.66) ; U1.45 21.96,113.83 22.9,112.89 22.9,110.34 23.45,109.79 23.45,103.05 31.01,95.49 v1(31.01,73.47) 31.01,51.73 29.11,49.83 29.11,14.99 v1(30.8,13.3) v1(18.1,13.3) 17.15,14.25 v1(10.51,14.25)
TL_DM: length 36.8
  TOP w0.2: v1(13.4,89.8) 14.13,89.8 14.88,90.54 15.69,90.54 17.71,92.57 21.19,92.57 v1(21.91,93.28)
  BOTTOM w0.2: U1.7 17.77,109.73 19.37,108.12 19.37,99.36 18.86,98.84 18.86,97.85 21.35,95.36 21.35,94.28 21.91,93.73 v1(21.91,93.28) ; v1(13.4,89.8) 13.34,89.86 R70.1
TL_DP: length 35.7
  TOP w0.2: v1(13.87,90.35) 14.48,90.96 15.51,90.96 17.54,93 20.52,93 v1(21.16,93.64)
  BOTTOM w0.2: R69.1 7.85,90.79 8.21,90.42 13.8,90.42 v1(13.87,90.35) ; U1.8 17.27,109.58 18.94,107.9 18.94,99.72 18.31,99.08 18.31,97.6 20.65,95.25 20.65,94.15 v1(21.16,93.64)
TL_IRCONTROL: length 101.1
  TOP w0.2: v1(22.5,94.54) 20.59,94.54 19.62,93.57 17.15,93.57 15.1,91.52 v1(13,91.52) ; v1(14.45,136.87) 14.93,136.87 16.27,135.53 19.7,135.53 21.27,133.96 22.43,133.96 v1(23.44,132.95)
  BOTTOM w0.2: v1(14.45,136.87) 8.43,136.87 7,135.43 7,133.36 4.9,131.27 4.9,120.82 3.84,119.76 3.84,102.3 5.39,100.75 5.39,99.53 10.12,94.81 10.12,93.31 11.91,91.52 v1(13,91.52) ; v1(22.5,94.54) 22.65,94.7 22.65,100 22.64,100.04 21.05,101.63 21.05,101.69 21.05,108.8 19.77,110.08 U1.3
  BOTTOM w0.5: R12.2 v1(23.44,132.95) 23.44,132.46 R13.2 22.41,132.45 R11.1 22.41,131.46 Q4.2
TL_IRIN: length 113.4
  TOP w0.2: v1(16.11,88.23) 16.73,88.84 22,88.84 v1(22.41,88.44) ; v1(22.05,134.58) 21.36,134.58 19.98,135.96 16.49,135.96 v1(14.75,137.7)
  BOTTOM w0.2: U1.4 19.27,111.33 19.37,111.23 19.37,109.92 20.65,108.63 20.65,101.69 20.65,101.56 20.65,101.46 22.24,99.87 22.25,99.83 22.25,98.39 TP36.1 22.25,96.94 22.25,95.65 21.9,95.3 21.9,94.33 22.67,93.55 22.67,89.18 22.41,88.92 v1(22.41,88.44) ; v1(16.11,88.23) 16.11,88.98 14.12,90.97 11.55,90.97 9.67,92.85 9.67,94.67 2.39,101.95 2.39,119.83 4.41,121.85 4.41,131.53 6.55,133.67 6.55,135.6 8.31,137.36 13.94,137.36 14.27,137.7 v1(14.75,137.7)
  BOTTOM w0.4: v1(22.05,134.58) 21.11,133.64 21.11,132.64 21.75,132 21.75,128.91 Q4.3
  BOTTOM w0.5: v1(22.05,134.58) 22.11,134.58 R10.1
TL_IROUT: length 35.4
  TOP w0.2: v1(3.86,126.48) 5.4,126.48 7.01,124.87 7.47,124.87 8.04,124.3 8.04,120.59 8.54,120.09 8.84,119.78 8.84,119.62 v1(9.08,119.38)
  BOTTOM w0.2: R9.1 10.62,137.9 8,137.9 6,135.9 6,133.8 3.86,131.65 v1(3.86,126.48) ; U1.21 14.26,116.33 14.06,116.53 11.2,119.38 v1(9.08,119.38)
  BOTTOM w0.5: R9.1 10.85,139.53 10.84,139.55 R8.2
TL_LED1: length 16.1
  TOP w0.2: v1(21.32,127.17) 21.32,128.22 19.13,130.42 18.34,130.42 v1(17.72,131.04)
  BOTTOM w0.2: v1(21.32,127.17) 21.32,127.16 21.24,127.08 21.24,126.78 21.08,126.62 21.08,120.21 20.99,120.12 20.99,120.09 19.77,118.87 U1.34 ; R2.1 v1(17.72,131.04)
TL_LED2: length 15.7
  TOP w0.2: v1(22.12,127.03) 22.12,127.99 v1(18.88,131.23)
  BOTTOM w0.2: R1.1 18.88,131.23 v1(18.88,131.23) ; U1.35 20.27,118.73 21.48,119.94 21.48,126.46 21.66,126.63 21.72,126.63 v1(22.12,127.03)
TL_ROW0: length 207.5
  TOP w0.2: SW22.2 20.6,38.42 v1(18.95,40.07) ; v1(18.96,27.98) 20.6,26.34 SW29.2 20.6,24.23 v1(19.73,23.36) ; v1(7.77,74.6) 7.77,76.46 5.67,78.56 v1(1.2,78.56) ; SW34.2 20.6,14.56 v1(19.65,15.51) ; v1(11.02,74.6) 12.44,76.01 14.67,76.01 15.95,74.73 SW1.2 ; v1(18.79,59.37) 20.6,61.18 SW8.2 ; v1(10.54,24.16) 7.53,21.15 2.65,21.15 v1(2.04,21.76) ; v1(19.16,52) 20.6,50.56 SW15.2
  BOTTOM w0.2: v1(18.95,40.07) 18.95,46.24 v1(18.05,47.13) ; v1(19.16,52) 18.79,52.36 v1(18.79,59.37) 19.68,59.37 20.3,58.75 21.02,58.75 27.9,65.63 27.9,73.3 24.65,76.55 24.65,100.3 22.65,102.3 22.65,109.46 21.65,110.46 21.65,111.83 21.97,112.15 21.97,112.5 21.64,112.83 U1.47 ; v1(10.54,24.16) 15.58,24.16 16.53,23.21 19.1,23.21 19.26,23.36 v1(19.73,23.36) 19.73,16.08 19.65,15.99 v1(19.65,15.51) ; v1(2.04,21.76) 0.69,23.11 0.69,62.32 1.5,63.13 1.5,78.24 1.2,78.53 v1(1.2,78.56) ; v1(18.76,34.99) 18.96,34.79 v1(18.96,27.98) ; v1(11.02,74.6) v1(7.77,74.6)
TL_ROW1: length 222
  TOP w0.2: v1(31.89,124.56) 32.82,124.56 34.55,122.83 SW9.2 ; v1(31.89,135.79) 33.3,134.37 SW2.2 ; v1(7.09,75.73) 7.09,76.3 5.78,77.61 v1(0.69,77.61) ; v1(34.1,97.96) SW16.2 34.1,99.13 32.79,100.44 30.76,100.44 29.35,99.03 29.35,98.74 v1(29.01,98.4) ; v1(16.15,82.6) 16.79,82.6 17.56,81.84 18.91,81.84 19.82,82.76 20.15,82.76 20.6,83.2 v1(20.6,83.5) 20.6,84.49 SW30.2 v1(20.6,85.1) ; v1(20.8,77.1) 24.95,77.1 v1(25.32,77.47)
  BOTTOM w0.2: v1(20.6,83.5) 20.6,83.02 20.8,82.82 v1(20.8,77.1) ; v1(16.15,82.6) 9.27,75.73 v1(7.09,75.73) ; v1(20.6,85.1) 21,85.5 21,91.92 18.02,94.9 v1(18.02,95.58) ; v1(25.32,77.47) 27.25,77.47 29.59,75.14 v1(29.59,74.4) ; U1.44 22.03,114.33 23.3,113.05 23.3,110.51 23.85,109.96 23.85,103.56 v1(29.01,98.4) ; v1(34.1,97.96) 34.1,74.25 v1(34.52,73.83) ; v1(31.89,124.56) v1(31.89,135.79) 31.89,138.07 27.57,142.38 6.89,142.38 3.82,139.31 3.82,134.58 0.49,131.24 0.49,113.21 0.48,113.2 0.48,112.08 0.49,112.08 0.49,78.29 0.69,78.08 v1(0.69,77.61)
TL_ROW2: length 134
  TOP w0.2: v1(22.2,111.15) 20.95,111.15 SW31.2 ; v1(7.62,131.85) 7.95,132.19 7.95,133.45 SW3.2 ; SW17.2 15.95,122.89 ; 15.95,122.89 15.95,123.05 14.48,124.52 12.33,124.52 10.82,123.02 10.82,122.58 ; 15.95,122.89 14.46,124.38 12.13,124.38 v1(11.33,123.59) ; v1(7.16,124.15) 6.65,123.64 SW10.2 6.65,121.26 5.05,119.67 v1(3.2,119.67) ; SW36.2 7.06,98.13 v1(7.06,98.77) ; v1(12.68,92.25) 15.03,92.25 16.89,94.11 19.57,94.11 20.65,95.19 23.68,95.19 25.2,93.66 v1(25.2,92.3)
  BOTTOM w0.2: U1.46 21.89,113.33 22.5,112.72 22.5,111.45 v1(22.2,111.15) 22.2,110.48 23.05,109.63 23.05,102.75 25.2,100.6 v1(25.2,92.3) ; v1(24.6,124) 24.6,127.25 24.1,127.75 23.03,127.75 23.03,127.75 22.18,127.75 21.25,127.75 20.9,128.1 20.9,129.35 19.85,130.4 19.85,131.75 19.45,132.15 19.45,133.85 19.3,134 18.15,134 16.65,135.5 9.2,135.5 8.35,134.65 8.35,132.58 v1(7.62,131.85) 7.16,131.39 v1(7.16,124.15) 7.77,124.15 8.33,123.59 v1(11.33,123.59) ; v1(3.2,119.67) 3.2,102.13 v1(4.84,100.48) ; v1(12.68,92.25) 12.11,92.25 10.78,93.59 10.78,95.06 v1(7.06,98.77)
TL_ROW3: length 113.4
  TOP w0.2: SW25.2 33.3,38.59 31.92,39.97 v1(31.08,39.97) ; v1(31.32,23.05) 31.85,23.05 33.3,24.5 SW32.2 33.3,26.23 31.68,27.85 v1(30.99,27.85) ; v1(25.1,74.95) 25.04,75.01 25.04,75.81 v1(26.08,76.85) ; SW35.2 33.3,14.13 v1(31.68,15.75) ; SW18.2 33.3,50.66 31.88,52.09 v1(30.39,52.09) ; v1(29.93,64.25) 32.05,64.25 33.1,63.2 SW11.2 33.1,61.27 31.45,59.63 v1(29.95,59.63)
  BOTTOM w0.2: U1.48 21.37,112.12 21.25,112 21.25,110.3 22.25,109.3 22.25,102.13 24.2,100.18 24.2,75.85 v1(25.1,74.95) ; v1(31.08,39.97) v1(31.08,47.15) ; v1(29.93,64.25) 28.3,65.88 28.3,74.63 v1(26.08,76.85) ; v1(31.32,23.05) 31.68,22.7 v1(31.68,15.75) ; v1(30.39,52.09) 30.39,59.18 v1(29.95,59.63) ; v1(30.99,27.85) v1(30.99,35.06)
TL_ROW4: length 153.7
  TOP w0.2: SW19.2 7.9,50.43 6.2,52.13 4.32,52.13 3.49,51.3 3.32,51.3 2.74,50.71 v1(2.74,50.24) ; 4.85,59.45 6.22,59.45 8.1,61.33 8.1,60.94 6.58,59.42 4.62,59.42 v1(4.02,60.01) ; v1(5.25,64.4) 6.51,64.4 8.1,62.81 SW12.2 ; v1(23.65,89.39) 23.17,89.39 23.06,89.27 15.87,89.27 v1(14.85,88.25) ; v1(3.72,15.16) 4.45,15.89 6.27,15.89 7.9,14.25 SW38.2 ; v1(3.23,39.19) 3.7,39.19 4.48,39.97 6.2,39.97 7.9,38.27 SW26.2 7.9,36.58 6.62,35.3 v1(4.19,35.3) ; v1(3.39,24.24) 4.43,23.21 6.62,23.21 7.9,24.48 SW37.2 7.9,26.15 6.09,27.96 4.5,27.96 v1(3.83,27.3)
  BOTTOM w0.2: v1(7.59,63.72) 7.59,67.08 5.8,68.87 v1(5.8,75.68) 6.62,76.5 9.2,76.5 14.85,82.15 v1(14.85,88.25) ; v1(4.19,35.3) 4.19,27.65 v1(3.83,27.3) ; v1(3.23,39.19) 2.74,39.68 v1(2.74,50.24) 2.74,58.73 v1(4.02,60.01) ; U1.1 20.77,110.21 21.85,109.13 21.85,101.97 23.67,100.14 23.67,94.95 23.65,94.92 v1(23.65,89.39) ; v1(3.39,24.24) 3.39,15.96 3.72,15.63 v1(3.72,15.16)
TL_RST: length 8.2
  BOTTOM w0.2: C4.1 22.03,119.86 20.77,118.6 U1.36
TL_SWS: length 6.4
  TOP w0.3: TP33.1 19.56,107.76 v1(17.84,107.76)
  BOTTOM w0.3: v1(17.84,107.76) 16.77,108.83 U1.9
TL_VBUS: length 36.6
  TOP w0.5: v1(19.95,91.4) 19.99,91.36 v1(19.99,90.78) 19.03,89.82 15.64,89.82 15.58,89.76 15.58,89.76 14.85,89.04 v1(14.22,89.04) v1(13.6,89.04)
  BOTTOM w0.4: J3.1 5.36,89.37 6.14,88.59 C42.1
  BOTTOM w0.5: C42.1 13.15,88.59 v1(13.6,89.04) v1(14.22,89.04) ; v1(19.99,90.78) 19.95,90.81 19.95,91.4 v1(19.95,91.4) 16.4,94.95 16.4,96.8 13.1,100.1 C39.1 13.1,101.77 13.12,101.79 U5.3 13.12,103.77 13.4,104.05 14.1,104.05 14.75,104.05 15.02,103.78 U5.1
TL_VDD: length 548.8
  TOP w0.5: TP21.1 17.79,102.74 J36.2 ; v1(8,102.56) v1(8,101.77) 8,101.39 8.67,100.72 8.67,95.95 9.07,95.56 9.07,91.87 v1(8.92,91.71)
  TOP w1: 21.52,67.83 v1(20.66,68.68) 20.74,68.76 21.52,68.76 ; 21.52,67.83 21.52,68.76 ; 21.52,67.83 22.07,67.28 ; CD1.1 22.07,67.28 ; 22.07,67.28 22.07,68.76 ; 21.52,68.76 22.07,68.76 ; 21.52,68.76 v1(20.66,69.62) 20.72,69.68 v1(22.31,69.68) 22.07,69.43 22.07,68.76
  BOTTOM w0.2: 16.08,119.14 16.27,118.95 16.27,118.68 ; 16.08,119.14 15.94,119 ; 16.08,119.14 16.01,119.21 15.63,119.21 ; 15.62,118.9 15.62,118.88 15.77,118.73 ; 15.62,118.9 15.77,118.75 ; 15.62,118.9 15.34,119.18 15.37,119.21 15.63,119.21 ; 15.77,118.83 15.94,119 ; 15.77,118.83 15.77,119.07 15.63,119.21 ; 15.77,118.83 15.77,118.75 ; 15.94,119 16.27,118.68 ; U1.27 16.27,118.68 ; 15.77,118.75 15.77,118.73 ; 15.77,118.73 U1.26
  BOTTOM w0.25: C27.2 12.64,112.41 13.55,113.33 U1.15
  BOTTOM w0.5: 20.35,70.45 20.18,70.63 20.18,71.3 ; 20.35,70.45 19.32,70.45 ; 20.35,70.45 20.66,70.45 ; 21.68,72.08 21.68,71.66 21.5,71.48 ; 21.68,72.08 22.2,71.55 ; 21.68,72.08 22.16,72.08 ; 21.68,72.08 21.68,72.55 ; 21.68,72.08 21.42,72.08 20.83,71.48 ; C28.2 15.03,119.48 15.34,119.18 ; C28.2 14.56,120.31 ; C28.2 15.03,120.46 ; 20.61,71.48 20.92,71.79 ; 20.61,71.48 20.49,71.48 20.18,71.79 ; 20.61,71.48 20.83,71.48 ; 20.92,71.79 20.18,71.79 ; 20.92,71.79 21.68,72.55 ; 19.32,70.08 18.61,70.79 18.61,89.92 5.45,103.07 5.45,118.22 6.43,119.19 6.43,121.17 7.55,122.29 11.66,122.29 13.63,120.31 14.56,120.31 ; R12.1 25.15,134.16 25.15,136.05 ; 20.18,71.79 20.18,71.3 ; 23.1,136.02 C26.1 23.52,136.05 C12.1 25.15,136.05 ; 23.1,136.02 23.04,136.08 23.04,136.51 ; 23.1,136.02 R10.2 ; 21.5,71.48 21.77,71.21 ; 21.5,71.48 20.83,71.48 ; 21.5,71.48 21.24,71.22 21.24,70.45 ; 21.77,71.21 C16.1 ; 21.77,71.21 21.64,71.07 21.64,70.45 ; 21.77,71.21 21.86,71.21 22.2,71.55 ; R4.2 v1(8.92,91.71) ; D4.A 25.15,138.82 25.15,136.05 ; C16.1 23.1,71.02 23.1,71.8 ; C16.1 21.64,70.45 ; C16.1 22.53,71.23 ; 22.2,71.55 22.53,71.23 ; 22.2,71.55 22.5,71.55 23.03,72.08 ; 22.16,72.08 22.7,72.08 ; 22.16,72.08 21.68,72.55 ; 22.7,72.08 22.7,72.44 22.99,72.14 23.1,72.14 ; 22.7,72.08 23.03,72.08 ; 15.03,120.46 14.88,120.31 14.56,120.31 ; 15.03,120.46 C7.2 ; 19.32,70.45 19.63,70.76 ; 19.32,70.45 18.96,70.82 19.57,70.82 19.63,70.76 ; 19.32,70.02 19.28,70.06 18.09,70.06 17.75,70.41 17.75,89.25 4.45,102.55 4.45,118.88 5.47,119.9 5.47,130.9 7.55,132.98 7.55,135.05 8.6,136.1 17.05,136.1 18.55,134.6 20.31,134.6 21.15,135.44 Q3.2 21.5,136.02 R10.2 ; J36.2 17.75,102.78 17.75,97.25 19.75,95.25 19.75,94 21.55,92.2 21.55,72.68 21.68,72.55 ; 20.83,71.48 20.66,71.31 20.66,70.45 ; R10.2 23.04,136.51 ; C27.2 12.64,111.77 12.08,111.21 10.69,111.21 8.85,109.36 8.85,103.41 v1(8,102.56) v1(8,101.77) 19.51,90.27 19.51,71.52 19.95,71.08 ; 23.04,136.51 23.05,136.51 R7.2 ; 20.18,71.3 19.95,71.08 ; 22.53,71.23 23.1,71.8 ; 20.66,70.45 21.24,70.45 ; 21.24,70.45 21.64,70.45 ; 23.03,72.08 23.1,72.14 ; 19.63,70.76 19.95,71.08 ; 23.1,71.8 23.1,72.14
  BOTTOM w1: 21.41,67.94 21.41,69.17 21.68,69.44 ; 21.41,67.94 CD1.1 22.31,68.8 ; 21.41,67.94 v1(20.66,68.68) ; 21.68,69.44 20.66,70.45 v1(20.66,69.62) v1(20.66,68.68) ; 21.68,69.44 22.31,68.8 ; v1(20.66,68.68) 19.32,70.02 19.32,70.45 ; 22.31,68.8 v1(22.31,69.68) 22.31,70.24 C16.1
  BOTTOM w2: BT1.1 6.91,5.72 ; BT1.1 4.9,4.51 4.9,5.51 5.3,5.91 ; BT1.1 5.3,5.91 ; 6.91,5.72 7.17,5.98 ; 6.91,5.72 6.91,8.99 ; 7.17,9.25 6.91,8.99 ; 7.17,9.25 8.9,10.97 ; 7.17,9.25 7.17,5.98 ; 6.91,8.99 5.66,7.74 5.3,7.74 ; 7.17,5.98 8.9,7.71 8.9,10.97 ; 5.3,5.91 5.3,6.9 ; 5.3,6.9 6.05,7.65 6.05,56.77 19.29,70.02 19.32,70.02 ; 5.3,6.9 5.3,7.74 ; 21.85,67.49 21.85,67.16 8.9,54.21 8.9,10.97 ; 5.3,7.74 7.35,9.79 7.35,55.37 v1(20.66,68.68)
TL_XC1: length 12.1
  BOTTOM w0.2: U1.40 21.8,116.33 22.06,116.06 22.81,116.06 24.95,113.92 24.95,111.55 25.13,111.37 26.88,111.37 27.83,112.32 Y1.3 C19.2
TL_XC2: length 10.3
  BOTTOM w0.2: C20.2 Y1.1 25.9,109.89 24.95,110.85 24.95,110.85 24.55,111.25 24.55,113.76 22.65,115.66 21.86,115.66 21.7,115.83 U1.41
N21000893: length 1.1
  TOP w0.5: D2.A 18.88,134.03 v1(18.88,133.43)
  BOTTOM w0.5: R1.2 v1(18.88,133.43)
N21007782: length 1.3
  TOP w0.5: D1.A 17.72,133.57 v1(17.72,133.46)
  BOTTOM w0.5: R2.2 v1(17.72,133.46)
N21036936: length 2.2
  TOP w0.2: v1(14.75,133.85) 14.54,133.85 U2.4
  BOTTOM w0.5: R3.2 C13.1 14.81,133.91 v1(14.75,133.85)
N21036981: length 0.9
  BOTTOM w0.2: C18.1 R17.2
N21036983: length 1.5
  TOP w0.2: U2.1 v1(11.7,134.2)
  BOTTOM w0.2: v1(11.7,134.2) 11.49,133.99 C18.2
N21081547: length 7.5
  BOTTOM w0.5: U5.5 15.02,107.15 C40.1 15.02,108.53 C41.1 15.66,108.54 16.3,107.9 16.3,106.77 J36.1
N21081898: length 2.4
  BOTTOM w0.2: R4.1 6.19,91.7 R69.2 6.08,90.67 J3.3
N21081900: length 1.5
  BOTTOM w0.2: J3.2 6.01,90.02 R70.2
N21088560: length 3.1
  BOTTOM w0.2: C10.2 12.57,116.8 14.04,115.33 U1.19
N21088582: length 5.1
  BOTTOM w0.3: U1.17 11.33,114.33 10.36,113.36 L3.1
N21088586: length 2.9
  BOTTOM w0.3: L3.2 12.73,113.36 12.74,113.34 13.23,113.83 U1.16
N21088616: length 2.6
  BOTTOM w0.3: U1.13 14.5,112.33 13.94,111.77 13.94,111.49 13.93,111.48 13.93,111.16 C8.2
N21092386: length 3.4
  BOTTOM w0.25: 22.18,117.33 U1.38
  BOTTOM w0.5: 22.18,117.33 22.83,117.33 L4.2 22.83,117.35 C30.2 C33.1
N21092388: length 2.6
  BOTTOM w0.25: U1.37 21.54,117.83 21.82,118.11 21.83,118.11 22.04,118.32 L4.1
  BOTTOM w0.5: L4.1 22.83,119.23 C31.1
N21092398: length 1.8
  BOTTOM w0.5: C33.2 C32.2 L7.1
N21092424: length 34.1
  BOTTOM w0.5: L7.2 C34.2 C35.2 35.59,117.35 35.59,112.98 33.15,112.98 33.15,111.73 35.65,111.73 35.65,110.48 33.15,110.48 33.15,109.23 35.65,109.23 35.65,107.98 33.15,107.98 33.15,106.73 35.65,106.73 35.65,105.28
N21108187: length 2.7
  BOTTOM w0.5: R7.1 20.6,137.5 20.6,137.5 D5.A
N21108227: length 16.3
  BOTTOM w0.5: R14.2 21.08,139.17 D4.C 21.19,139.73 22.09,140.63 25.7,140.63 26.18,140.15 26.18,133.32 25.31,132.45 R13.1
N21108333: length 1.3
  BOTTOM w0.5: R9.2 11.85,138.13 Q2.1
N21108349: length 3.1
  BOTTOM w0.5: Q2.3 15.37,139.16 R15.1 D5.C
N21108369: length 5.3
  TOP w0.5: v1(21.76,133.11) 21.16,132.51 v1(20.14,132.51)
  BOTTOM w0.5: R11.2 22.11,133.46 v1(21.76,133.11) ; Q4.1 20.74,131.9 v1(20.14,132.51) Q3.3
N21108379: length 5.7
  BOTTOM w0.4: Q3.1 18.65,135.67 18.12,136.2 18.12,138.87 ; 18.12,138.87 18.12,138.9 18.37,139.16 ; 18.12,138.87 R15.2 18.37,139.16 ; R14.1 18.85,139.16 18.37,139.16

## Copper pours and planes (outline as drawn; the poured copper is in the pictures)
GND on TOP: 4,0.3 1.38,1.38 0.3,4 0.3,144 0.8,145.2 2,145.7 10,145.7 10.49,145.49 10.7,145 10.7,143.8 11.08,142.88 12,142.5 24.2,142.5 25.12,142.88 25.5,143.8 25.5,145 25.71,145.49 26.2,145.7 34.2,145.7 35.4,145.2 35.9,144 35.9,124.52 30.65,119.27 30.65,116.54 30.6,100.4 35.9,100.4 35.9,4 34.82,1.38 32.2,0.3 ; 3 cut-outs
GND on BOTTOM: 4,0.3 1.38,1.38 0.3,4 0.3,144 0.8,145.2 2,145.7 10,145.7 10.49,145.49 10.7,145 10.7,143.8 11.08,142.88 12,142.5 24.2,142.5 25.12,142.88 25.5,143.8 25.5,145 25.71,145.49 26.2,145.7 34.2,145.7 35.4,145.2 35.9,144 35.9,124.51 30.65,119.26 30.65,118.11 30.64,118.11 22.25,118.11 22.25,116.58 30.65,116.58 30.65,100.4 35.9,100.4 35.9,4 34.82,1.38 32.2,0.3 ; 46 cut-outs

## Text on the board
Ref Des/Silkscreen Bottom: B7 | B6 | B5 | B4 | B1/TX | B0/RX | SWS | A2/UTX | A0/URX
User.Comments: AMJ-151029 | AMJ-160130 | +
Ref Des/Silkscreen Top: B6 | B5 | B7 | B4 | B1/TX | B0/RX | 32OUT | 32IN | GND | SWS | VDD | 2018-11-01 | C1T139A5_V1.4 | C0
COMPVAL_TYPE_BOTTOM: FIGURE | SIZE | 0.3 | 0.5 | 0.7 | 0.9 | 0.6 | 1.55x0.45 | 3.5x0.7 | DRILL CHART: TOP to BOTTOM | ALL UNITS ARE IN MILLIMETERS | PLATED | NON-PLATED | QTY | 557 | 2 | 12
BODY_CENTER: +
